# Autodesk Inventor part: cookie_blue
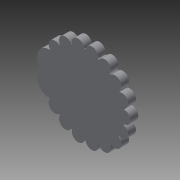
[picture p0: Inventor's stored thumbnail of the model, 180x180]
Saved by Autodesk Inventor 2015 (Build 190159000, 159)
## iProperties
Created: 2017-04
Part Number: cookie_blue
Material: Generic
Document SubType Name: Modeling
Designer: mcalderon
Density: 1 g/cm^3
Appearance: Default
Author: mcalderon
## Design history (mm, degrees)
sketch "Sketch1"
  geometry: L1 (25, 0)-(-25, 0); L2 (0, 25)-(0, -25); A1 r 4 centre (25, 0) between (24.68, -3.987) and (24.68, 3.987); A2 r 4 centre (23.492, 8.551) between (24.555, 4.694) and (21.828, 12.188); A3 r 4 centre (19.151, 16.07) between (21.469, 12.81) and (16.343, 18.918); A4 r 4 centre (12.5, 21.651) between (15.793, 19.38) and (8.887, 23.367); A5 r 4 centre (4.341, 24.62) between (8.212, 23.613) and (0.359, 24.997); A6 r 4 centre (-4.341, 24.62) between (-0.359, 24.997) and (-8.212, 23.613); A7 r 4 centre (-12.5, 21.651) between (-8.887, 23.367) and (-15.793, 19.38); A8 r 4 centre (-19.151, 16.07) between (-16.343, 18.918) and (-21.469, 12.81); A9 r 4 centre (-23.492, 8.551) between (-21.828, 12.188) and (-24.555, 4.694); A10 r 4 centre (-25, 0) between (-24.68, 3.987) and (-24.68, -3.987); A11 r 4 centre (-23.492, -8.551) between (-24.555, -4.694) and (-21.828, -12.188); A12 r 4 centre (-19.151, -16.07) between (-21.469, -12.81) and (-16.343, -18.918); A13 r 4 centre (-12.5, -21.651) between (-15.793, -19.38) and (-8.887, -23.367); A14 r 4 centre (-4.341, -24.62) between (-8.212, -23.613) and (-0.359, -24.997); A15 r 4 centre (4.341, -24.62) between (0.359, -24.997) and (8.212, -23.613); A16 r 4 centre (12.5, -21.651) between (8.887, -23.367) and (15.793, -19.38); A17 r 4 centre (19.151, -16.07) between (16.343, -18.918) and (21.469, -12.81); A18 r 4 centre (23.492, -8.551) between (21.828, -12.188) and (24.555, -4.694); A19 r 25 centre (0, 0) between (21.469, -12.81) and (21.828, -12.188); A20 r 25 centre (0, 0) between (15.793, -19.38) and (16.343, -18.918); A21 r 25 centre (0, 0) between (8.212, -23.613) and (8.887, -23.367); A22 r 25 centre (0, 0) between (-0.359, -24.997) and (0.359, -24.997); A23 r 25 centre (0, 0) between (-8.887, -23.367) and (-8.212, -23.613); A24 r 25 centre (0, 0) between (-16.343, -18.918) and (-15.793, -19.38); A25 r 25 centre (0, 0) between (-21.828, -12.188) and (-21.469, -12.81); A26 r 25 centre (0, 0) between (-24.68, -3.987) and (-24.555, -4.694); A27 r 25 centre (0, 0) between (-24.555, 4.694) and (-24.68, 3.987); A28 r 25 centre (0, 0) between (-21.469, 12.81) and (-21.828, 12.188); A29 r 25 centre (0, 0) between (-15.793, 19.38) and (-16.343, 18.918); A30 r 25 centre (0, 0) between (-8.212, 23.613) and (-8.887, 23.367); A31 r 25 centre (0, 0) between (0.359, 24.997) and (-0.359, 24.997); A32 r 25 centre (0, 0) between (8.887, 23.367) and (8.212, 23.613); A33 r 25 centre (0, 0) between (16.343, 18.918) and (15.793, 19.38); A34 r 25 centre (0, 0) between (21.828, 12.188) and (21.469, 12.81); A35 r 25 centre (0, 0) between (24.555, -4.694) and (24.68, -3.987); A36 r 25 centre (0, 0) between (24.68, 3.987) and (24.555, 4.694); 1 further point
  constraints: 74 point on circle, 36 centre point, 4 end point, 1 coincident, 1 perpendicular, 73 other
  dimensions: "d1" = 8 diameter of A1; "d4" = 360 deg dimension on point (0, 0) L1.start (derived)
extrude "Extrusion1" new body sketch "Sketch1" distance "d6" = 5; taper "d7" = 0 deg
sketch "Sketch2"
  geometry: L1 (5.643, -19.187)-(5.643, 19.187); L2 (-31.254, 0)-(33.406, 0); C1 r 8 at (-22.544, 5.431); C2 r 8 at (-22.544, -5.431); A1 r 20 centre (0, 0) between (5.643, -19.187) and (5.643, 19.187); 1 further point
  constraints: 4 end point, 3 centre point, 2 point on circle, 1 coincident, 1 horizontal, 1 symmetric about line, 1 vertical, 1 other
  dimensions: "d9" = 16 diameter of C1
extrude "Extrusion4" join sketch "Sketch2" distance "d14" = 2; taper "d15" = 0 deg
sketch "Sketch5"
  geometry: L1 (-28.509, 0)-(-16.729, 0); L2 (-22.619, -13.304)-(-22.619, 13.431); C1 r 8 at (-22.544, 5.431); C2 r 8 at (-22.544, -5.431); A1 r 8 centre (-22.544, 5.431) between (-16.67, 0) and (-28.418, 0) reference; 1 further point
  constraints: 4 end point, 2 centre point, 1 coincident, 1 horizontal, 1 point on circle, 1 symmetric about line, 1 vertical, 1 other
  dimensions: "d16" = 16 diameter of C1
extrude "Extrusion5" join sketch "Sketch5" distance "d17" = 7; taper "d18" = 0 deg
sketch "Sketch6"
  geometry: C1 r 3.247 at (-26.213, -4.124); C2 r 3 at (-19.435, 3.798); 1 further point
  constraints: 2 centre point
  dimensions: "d19" = 6 diameter of C2
extrude "Extrusion6" join sketch "Sketch6" distance "d20" = 1; taper "d21" = 0 deg
body "Solid1"
